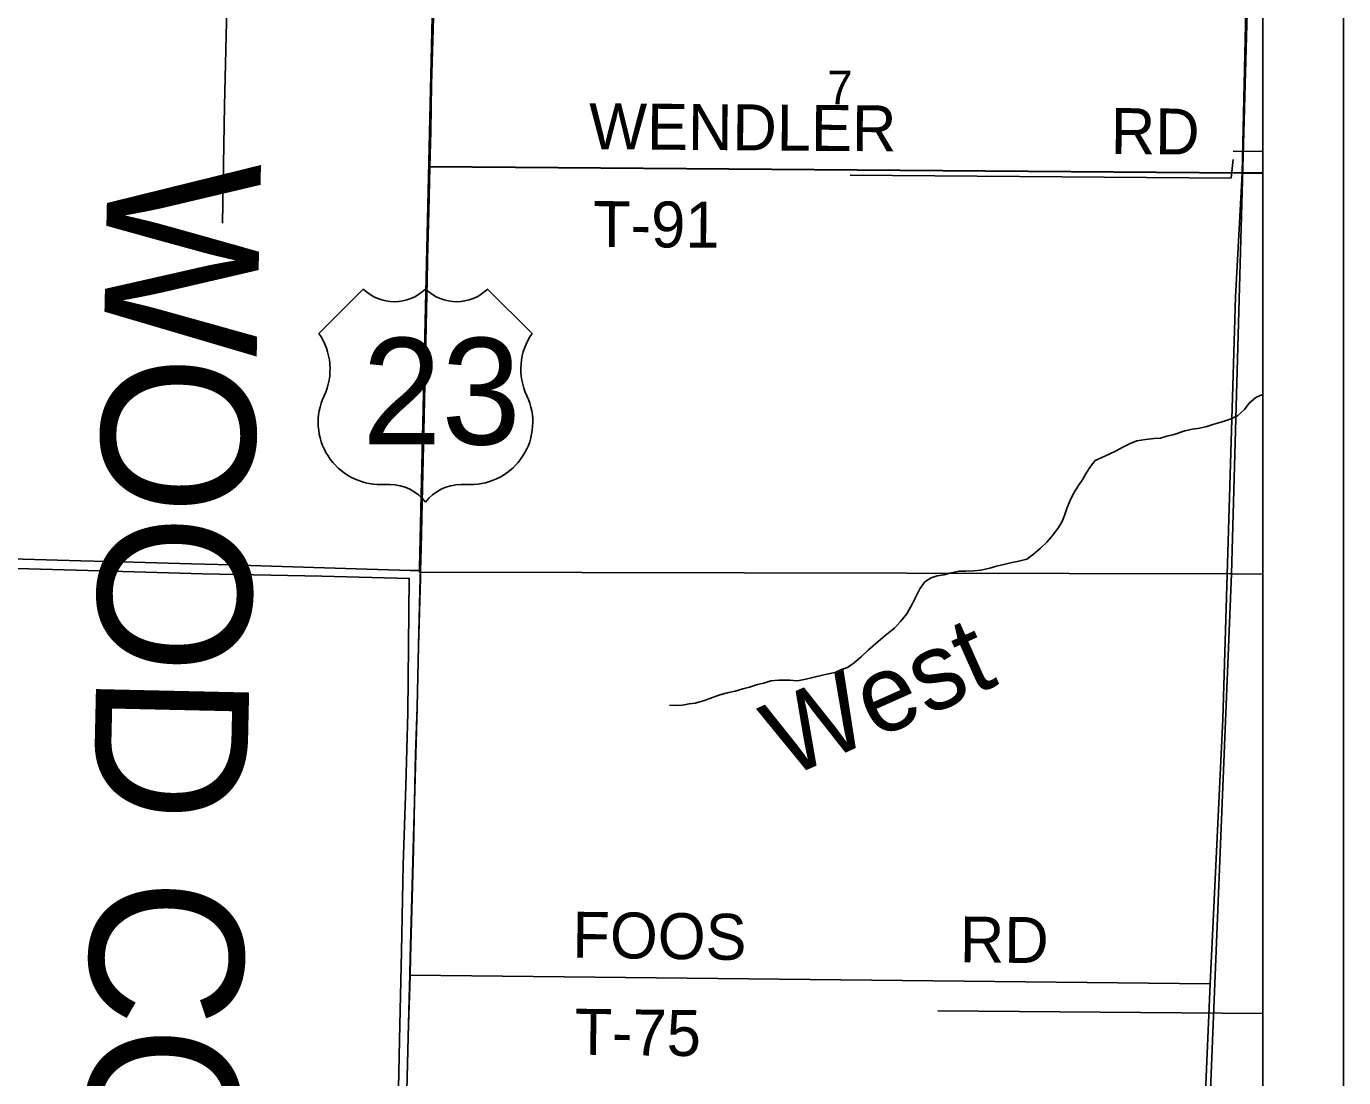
# Model space of a CAD drawing. Extents: x -8.3 to 42.1, y 0 to 22.
# Drawn here: x 7.372 to 9, y 15.682 to 16.982 of the extents above; entities that cross this region are included whole.
import ezdxf

# ---------------------------------------------------------------- set-up
doc = ezdxf.new("R2010")
doc.units = 0
for name, color, linetype in [('Default', 7, 'Continuous'), ('GM_X_County_Text', 7, 'Continuous'), ('GM_X_Minor_River', 7, 'Continuous'), ('GM_X_Minor_River_Text', 7, 'Continuous'), ('GM_X_Section', 7, 'Continuous'), ('GM_X_Section_Text', 7, 'Continuous'), ('GM_X_Township_Road', 7, 'Continuous'), ('GM_X_Township_Road_Text', 7, 'Continuous'), ('GM_X_US_Location', 7, 'Continuous'), ('GM_X_US_Route', 7, 'Continuous'), ('GM_X_US_Shield', 7, 'Continuous'), ('SH_Cut_Line', 7, 'Continuous'), ('SH_Data', 7, 'Continuous')]:
    doc.layers.add(name, color=color, linetype=linetype)

msp = doc.modelspace()

# ---------------------------------------------------------------- linework, layer by layer
at = {"layer": 'Default'}
for points in [[(8.9, 16.3044), (8.9, 17.309), (8.8895, 17.3091), (8.8613, 16.3047)], [(8.9, 15.3104), (8.9, 16.3044), (8.8613, 16.3047), (8.821, 15.3114)]]:
    msp.add_lwpolyline(points, close=True, dxfattribs=at)
at = {"layer": 'GM_X_Minor_River'}
for p, q in [((8.9, 16.8274), (8.8633, 16.8276)), ((8.8634, 16.8173), (8.8611, 16.7946)), ((8.8611, 16.7942), (8.3898, 16.7981)), ((8.9, 15.7609), (8.4982, 15.7643))]:
    msp.add_line(p, q, dxfattribs=at)
for points in [[(7.6193, 17.0045), (7.6167, 16.8842), (7.6142, 16.7386)], [(8.9, 16.5267), (8.8998, 16.5266), (8.8914, 16.5228), (8.8831, 16.5159), (8.8775, 16.5079), (8.8688, 16.5003), (8.8597, 16.496), (8.8498, 16.493), (8.8384, 16.4895), (8.8309, 16.4872), (8.8221, 16.4848), (8.813, 16.4837), (8.8036, 16.4817), (8.7907, 16.4771), (8.7816, 16.4751), (8.7736, 16.4728), (8.7657, 16.472), (8.755, 16.4708), (8.7444, 16.4692), (8.7353, 16.4654), (8.727, 16.4616), (8.7187, 16.457), (8.7103, 16.4527), (8.7009, 16.4485), (8.6929, 16.4451), (8.6872, 16.4374), (8.6816, 16.4294), (8.6774, 16.4218), (8.6721, 16.4142), (8.6665, 16.4051), (8.6616, 16.3948), (8.6578, 16.3857), (8.6548, 16.3769), (8.6515, 16.3689), (8.6466, 16.3609), (8.6401, 16.3522), (8.633, 16.3441), (8.6254, 16.3365), (8.6167, 16.3293), (8.6084, 16.3231), (8.5985, 16.3204), (8.5902, 16.3189), (8.5818, 16.3169), (8.5708, 16.3142), (8.5625, 16.3119), (8.5515, 16.3095), (8.5428, 16.3084), (8.5329, 16.3083), (8.5246, 16.3079), (8.5132, 16.3055), (8.5056, 16.3036), (8.4977, 16.3024), (8.4901, 16.2997), (8.4825, 16.2948), (8.4761, 16.2864), (8.467, 16.2681), (8.4599, 16.2552), (8.4523, 16.246), (8.4448, 16.2376), (8.4353, 16.23), (8.4274, 16.2235), (8.4122, 16.2105), (8.4039, 16.2025), (8.3949, 16.1948), (8.3869, 16.1891), (8.3793, 16.1864), (8.3714, 16.1826), (8.3634, 16.181), (8.3558, 16.1794), (8.3437, 16.1767), (8.3354, 16.1744), (8.3247, 16.1724), (8.3153, 16.1732), (8.3016, 16.1731), (8.2921, 16.1723), (8.2834, 16.1696), (8.2754, 16.168), (8.2656, 16.1645), (8.2572, 16.1626), (8.2478, 16.1595)], [(6.8579, 16.325), (7.0433, 16.3198), (7.1925, 16.3161), (7.3453, 16.312), (7.477, 16.3081), (7.5894, 16.305), (7.737, 16.3018), (7.8449, 16.2992), (7.8434, 16.1334), (7.8408, 16.0427), (7.8376, 15.9449), (7.8354, 15.8379), (7.833, 15.7279), (7.8304, 15.6084)], [(8.2478, 16.1595), (8.2402, 16.1579), (8.2288, 16.1552), (8.2197, 16.1518), (8.2099, 16.1483), (8.1985, 16.1448), (8.1909, 16.144), (8.1826, 16.1425), (8.1746, 16.142), (8.1666, 16.1424)]]:
    msp.add_lwpolyline(points, dxfattribs=at)
at = {"layer": 'GM_X_Section'}
msp.add_lwpolyline([(7.8808, 17.3192), (8.8895, 17.3091), (8.8613, 16.3047), (7.8576, 16.3068), (7.8577, 16.3121), (7.8807, 17.3166)], close=True, dxfattribs=at)
at = {"layer": 'GM_X_Township_Road'}
msp.add_line((7.846, 15.8083), (8.835, 15.7975), dxfattribs=at)
for points in [[(7.8748, 16.993), (7.8741, 16.965), (7.8727, 16.9246), (7.8724, 16.9106), (7.8713, 16.8531), (7.8702, 16.8088), (8.8743, 16.8009), (8.9, 16.8007), (8.9, 20.9)], [(8.8745, 16.8004), (8.882, 17.1313), (8.8875, 17.3037)], [(7.8403, 15.6006), (7.844, 15.7482), (7.8454, 15.7948), (7.8458, 15.8089), (7.8463, 15.8306), (7.85, 15.9642), (7.8514, 16.0233), (7.8529, 16.0823), (7.8546, 16.1398), (7.8564, 16.216), (7.8585, 16.2999), (7.8587, 16.3095), (7.8594, 16.3372), (7.8611, 16.4118), (7.8629, 16.4817), (7.8642, 16.5392), (7.8652, 16.592), (7.8666, 16.6511), (7.8668, 16.6682), (7.8672, 16.6915), (7.8672, 16.6946), (7.8687, 16.7536), (7.8702, 16.8088), (7.8713, 16.8531), (7.8724, 16.9106), (7.8727, 16.9246), (7.8741, 16.965), (7.8748, 16.993)], [(8.9, 14.1), (8.9, 16.8007), (8.8743, 16.8009), (7.8702, 16.8088), (7.8687, 16.7536), (7.8672, 16.6946), (7.8672, 16.6915), (7.8668, 16.6682), (7.8666, 16.6511), (7.8652, 16.592), (7.8642, 16.5392), (7.8629, 16.4817), (7.8611, 16.4118), (7.8594, 16.3372), (7.8587, 16.3095), (7.8585, 16.2999), (7.8564, 16.216), (7.8546, 16.1398), (7.8529, 16.0823), (7.8514, 16.0233), (7.85, 15.9642), (7.8463, 15.8306), (7.8458, 15.8089), (7.8454, 15.7948), (7.844, 15.7482), (7.8403, 15.6006)], [(7.8704, 16.8082), (8.8745, 16.8004), (8.9, 16.8001)], [(8.8198, 15.3016), (8.828, 15.6349), (8.835, 15.7975), (8.8508, 16.125), (8.8664, 16.6469), (8.8745, 16.8004)], [(6.8503, 16.3361), (6.8538, 16.3367), (6.8579, 16.3368), (6.8812, 16.3359), (6.9123, 16.3348), (6.9713, 16.3335), (7.0676, 16.331), (7.0956, 16.3303), (7.1282, 16.3296), (7.2246, 16.3271), (7.2618, 16.3259), (7.3675, 16.3231), (7.439, 16.3209), (7.5042, 16.3193), (7.5757, 16.3171), (7.6083, 16.3162), (7.6487, 16.3151), (7.7792, 16.3111), (7.846, 16.3088), (7.8522, 16.3089), (7.8589, 16.309)]]:
    msp.add_lwpolyline(points, dxfattribs=at)
at = {"layer": 'GM_X_US_Route'}
for points in [[(7.8704, 16.8082), (7.8716, 16.8525), (7.8726, 16.9101), (7.8729, 16.924), (7.8743, 16.9644), (7.875, 16.9924)], [(7.8405, 15.6001), (7.8442, 15.7477), (7.8456, 15.7943), (7.846, 15.8083), (7.8466, 15.83), (7.8502, 15.9637), (7.8516, 16.0227), (7.8532, 16.0818), (7.8548, 16.1393), (7.8566, 16.2154), (7.8587, 16.2993), (7.8589, 16.309), (7.8596, 16.3366), (7.8613, 16.4112), (7.8632, 16.4811), (7.8644, 16.5386), (7.8655, 16.5915), (7.8668, 16.6505), (7.867, 16.6676), (7.8674, 16.6909), (7.8674, 16.694), (7.869, 16.7531), (7.8704, 16.8082)]]:
    msp.add_lwpolyline(points, dxfattribs=at)
at = {"layer": 'GM_X_US_Shield'}
for p, q in [((7.7881, 16.657), (7.7332, 16.6021)), ((7.9969, 16.6021), (7.9419, 16.657)), ((7.8101, 16.4153), (7.8211, 16.4153)), ((7.909, 16.4153), (7.92, 16.4153))]:
    msp.add_line(p, q, dxfattribs=at)
for centre, radius, start, end in [((7.8266, 16.6963), 0.0549, 225.573, 314.427), ((7.9035, 16.6963), 0.0549, 225.573, 314.427), ((7.6702, 16.558), 0.0769, 334.5471, 35.0009), ((8.0599, 16.558), 0.0769, 144.9991, 205.4529), ((7.8093, 16.4922), 0.0769, 154.8319, 270.6383), ((7.9208, 16.4922), 0.0769, 269.3617, 25.1681), ((7.8211, 16.3604), 0.0549, 36.8699, 90), ((7.909, 16.3604), 0.0549, 90, 143.1301)]:
    msp.add_arc(centre, radius, start, end, dxfattribs=at)
at = {"layer": 'SH_Cut_Line'}
for points in [[(8.9, 14.1), (8.9, 20.9)], [(7.8403, 15.6006), (7.844, 15.7482), (7.8454, 15.7948), (7.8458, 15.8089), (7.8463, 15.8306), (7.85, 15.9642), (7.8514, 16.0233), (7.8529, 16.0823), (7.8546, 16.1398), (7.8564, 16.216), (7.8585, 16.2999), (7.8587, 16.3095), (7.8594, 16.3372), (7.8611, 16.4118), (7.8629, 16.4817), (7.8642, 16.5392), (7.8652, 16.592), (7.8666, 16.6511), (7.8668, 16.6682), (7.8672, 16.6915), (7.8672, 16.6946), (7.8687, 16.7536), (7.8702, 16.8088), (7.8713, 16.8531), (7.8724, 16.9106), (7.8727, 16.9246), (7.8741, 16.965), (7.8748, 16.993)], [(7.8748, 16.993), (7.8741, 16.965), (7.8727, 16.9246), (7.8724, 16.9106), (7.8713, 16.8531), (7.8702, 16.8088), (7.8687, 16.7536), (7.8672, 16.6946), (7.8672, 16.6915), (7.8668, 16.6682), (7.8666, 16.6511), (7.8652, 16.592), (7.8642, 16.5392), (7.8629, 16.4817), (7.8611, 16.4118), (7.8594, 16.3372), (7.8587, 16.3095), (7.8585, 16.2999), (7.8564, 16.216), (7.8546, 16.1398), (7.8529, 16.0823), (7.8514, 16.0233), (7.85, 15.9642), (7.8463, 15.8306), (7.8458, 15.8089), (7.8454, 15.7948), (7.844, 15.7482), (7.8403, 15.6006)]]:
    msp.add_lwpolyline(points, dxfattribs=at)
at = {"layer": 'SH_Data'}
for p, q in [((9, 21), (9, 14)), ((8.9, 20.9), (8.9, 14.1))]:
    msp.add_line(p, q, dxfattribs=at)

# ---------------------------------------------------------------- texts
at = {"layer": 'GM_X_County_Text'}
msp.add_text('WOOD COUNTY', height=0.189394, rotation=268.7124, dxfattribs=at).set_placement((7.4724, 16.8159))
at = {"layer": 'GM_X_Minor_River_Text'}
msp.add_text('West', height=0.09475, rotation=24.0489, dxfattribs=at).set_placement((8.3116, 16.0512))
at = {"layer": 'GM_X_Section_Text'}
msp.add_text('7', height=0.0419, rotation=0, dxfattribs=at).set_placement((8.3618, 16.8854))
at = {"layer": 'GM_X_Township_Road_Text'}
for s, rotation, p in [('WENDLER', 359.5774, (8.067, 16.8301)), ('RD', 359.5045, (8.712, 16.8242)), ('T-91', 359.6452, (8.0721, 16.7091)), ('FOOS', 359.1925, (8.0463, 15.8301)), ('RD', 359.5064, (8.5254, 15.8242)), ('T-75', 359.2931, (8.049, 15.7101))]:
    msp.add_text(s, height=0.05682, rotation=rotation, dxfattribs=at).set_placement(p)
at = {"layer": 'GM_X_US_Location'}
for s in ['0', '/']:
    msp.add_text(s, height=0.000189, dxfattribs=at).set_placement((7.865, 16.5296))
msp.add_text('23', height=0.000189, rotation=0, dxfattribs=at).set_placement((7.8259, 16.4904))
at = {"layer": 'GM_X_US_Shield'}
msp.add_text('23', height=0.13184, dxfattribs=at).set_placement((7.7868, 16.4648))

doc.saveas('drawing.dxf')
